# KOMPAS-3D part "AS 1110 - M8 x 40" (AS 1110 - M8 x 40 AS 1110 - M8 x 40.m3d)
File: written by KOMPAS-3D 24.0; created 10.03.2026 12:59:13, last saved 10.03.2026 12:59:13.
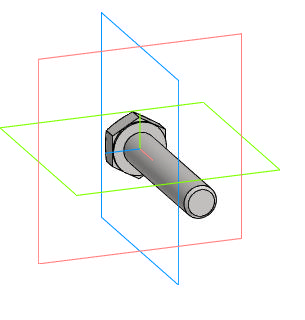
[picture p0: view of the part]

Document properties: Автор: R2D2; Полное имя файла: E:\Работа\Зайцев\BV3232P(4pc)-FP-3WL-F-ISO-H Кран шаровой DN.ru Ду15-100 Ру16\DN65\исходные материалы\AS 1110 - M8 x 40 AS 1110 - M8 x 40.m3d

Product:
- Body: Solid1  | qty 1
- Part/product: AS 1110 - M8 x 40
    Комментарий: Болты и винты   шестигранные точные   метрические ISO
    additional columns: Сталь, мягкая

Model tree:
1. Solid1  (labels: Solid1)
